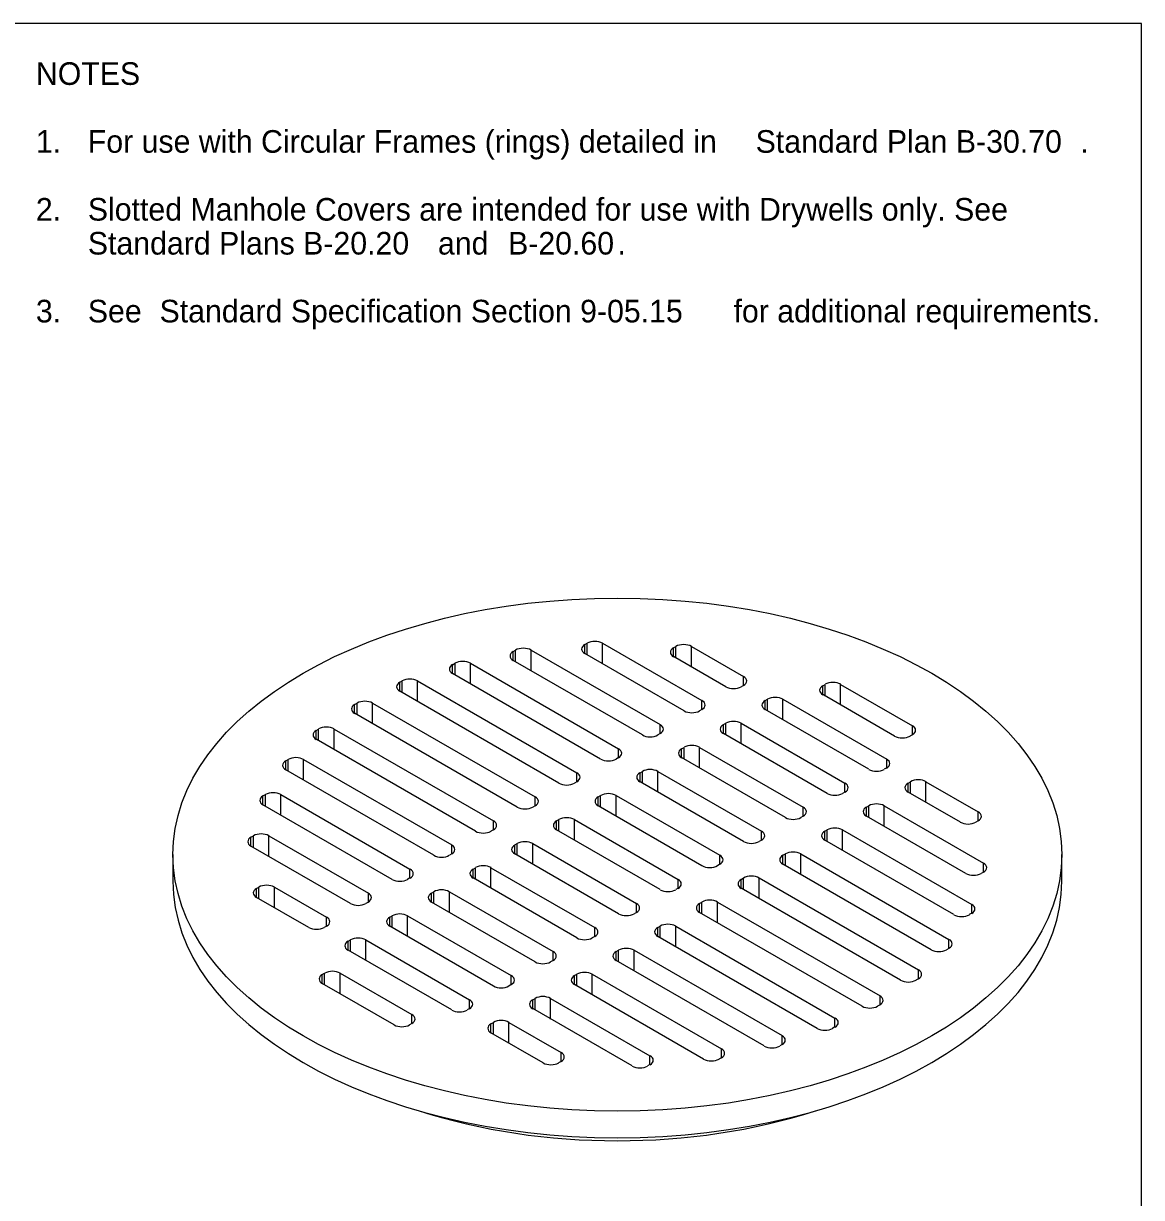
# Model space of a CAD drawing. Extents: x 99862 to 103151, y 100000 to 102076.
# Drawn here: x 102163 to 103151, y 101038 to 102076 of the extents above; entities that cross this region are included whole.
import ezdxf

# ---------------------------------------------------------------- set-up
doc = ezdxf.new("R2010")
doc.units = 0
for name, color, linetype in [('Level 1', 7, 'Continuous'), ('Level 18', 7, 'Continuous'), ('Level 20', 7, 'Continuous'), ('Level 60', 7, 'Continuous')]:
    doc.layers.add(name, color=color, linetype=linetype)

msp = doc.modelspace()

# ---------------------------------------------------------------- linework, layer by layer
at = {"layer": 'Level 1'}
msp.add_lwpolyline([(99862, 99999.5), (103151, 99999.5), (103151, 102075.5), (99862, 102075.5)], close=True, dxfattribs=at)
at = {"layer": 'Level 18'}
for p, q in [((102658.9, 101526.3), (102661, 101527.6)), ((102661, 101517.2), (102661, 101527.6)), ((102674.7, 101527.6), (102762.5, 101476.9)), ((102674.7, 101509.3), (102674.7, 101527.6)), ((102595.8, 101520.2), (102597.9, 101521.5)), ((102595.8, 101512.3), (102595.8, 101520.2)), ((102597.9, 101511.1), (102597.9, 101521.5)), ((102611.6, 101521.5), (102725.7, 101455.6)), ((102611.6, 101503.2), (102611.6, 101521.5)), ((102658.9, 101518.4), (102658.9, 101526.3)), ((102746.7, 101467.7), (102658.9, 101518.4)), ((102737.5, 101523.6), (102739.6, 101524.8)), ((102737.5, 101515.7), (102737.5, 101523.6)), ((102739.6, 101514.4), (102739.6, 101524.8)), ((102753.3, 101524.8), (102799.4, 101498.1)), ((102753.3, 101506.5), (102753.3, 101524.8)), ((102542.2, 101508.6), (102544.3, 101509.9)), ((102542.2, 101500.7), (102542.2, 101508.6)), ((102544.3, 101499.5), (102544.3, 101509.9)), ((102558, 101509.9), (102688.8, 101434.3)), ((102558, 101491.6), (102558, 101509.9)), ((102709.9, 101446.5), (102595.8, 101512.3)), ((102783.6, 101489), (102737.5, 101515.7)), ((102673, 101425.2), (102542.2, 101500.7)), ((102799.4, 101490.2), (102799.4, 101498.1)), ((102495.4, 101493.1), (102497.5, 101494.3)), ((102495.4, 101485.2), (102495.4, 101493.1)), ((102497.5, 101483.9), (102497.5, 101494.3)), ((102511.2, 101494.3), (102652, 101413)), ((102511.2, 101476), (102511.2, 101494.3)), ((102799.4, 101490.2), (102797.3, 101489)), ((102869.3, 101490), (102871.4, 101491.2)), ((102869.3, 101482.1), (102869.3, 101490)), ((102871.4, 101480.9), (102871.4, 101491.2)), ((102885.1, 101491.2), (102948.5, 101454.6)), ((102885.1, 101473), (102885.1, 101491.2)), ((102636.2, 101403.9), (102495.4, 101485.2)), ((102762.5, 101469), (102762.5, 101476.9)), ((102818.4, 101476.9), (102820.5, 101478.1)), ((102818.4, 101469), (102818.4, 101476.9)), ((102820.5, 101467.7), (102820.5, 101478.1)), ((102834.1, 101478.1), (102925.8, 101425.2)), ((102834.1, 101459.8), (102834.1, 101478.1)), ((102932.7, 101445.5), (102869.3, 101482.1)), ((102455.6, 101473.5), (102457.7, 101474.7)), ((102455.6, 101465.6), (102455.6, 101473.5)), ((102599.3, 101382.6), (102455.6, 101465.6)), ((102457.7, 101464.3), (102457.7, 101474.7)), ((102471.4, 101474.7), (102615.1, 101391.7)), ((102471.4, 101456.4), (102471.4, 101474.7)), ((102762.5, 101469), (102760.4, 101467.7)), ((102910, 101416.1), (102818.4, 101469)), ((102725.7, 101447.7), (102725.7, 101455.6)), ((102781.5, 101455.6), (102783.6, 101456.8)), ((102781.5, 101447.7), (102781.5, 101455.6)), ((102783.6, 101446.5), (102783.6, 101456.8)), ((102797.3, 101456.8), (102888.9, 101403.9)), ((102797.3, 101438.6), (102797.3, 101456.8)), ((102948.5, 101446.7), (102948.5, 101454.6)), ((102421.7, 101450.5), (102423.8, 101451.7)), ((102421.7, 101442.6), (102421.7, 101450.5)), ((102423.8, 101441.4), (102423.8, 101451.7)), ((102437.5, 101451.7), (102578.2, 101370.5)), ((102437.5, 101433.5), (102437.5, 101451.7)), ((102725.7, 101447.7), (102723.6, 101446.5)), ((102873.1, 101394.8), (102781.5, 101447.7)), ((102948.5, 101446.7), (102946.4, 101445.5)), ((102562.4, 101361.3), (102421.7, 101442.6)), ((102688.8, 101426.4), (102688.8, 101434.3)), ((102744.6, 101434.3), (102746.7, 101435.5)), ((102744.6, 101426.4), (102744.6, 101434.3)), ((102746.7, 101425.2), (102746.7, 101435.5)), ((102760.4, 101435.5), (102852.1, 101382.6)), ((102760.4, 101417.3), (102760.4, 101435.5)), ((102394.7, 101423.5), (102396.8, 101424.7)), ((102394.7, 101415.6), (102394.7, 101423.5)), ((102396.8, 101414.4), (102396.8, 101424.7)), ((102410.5, 101424.7), (102541.4, 101349.2)), ((102410.5, 101406.5), (102410.5, 101424.7)), ((102688.8, 101426.4), (102686.7, 101425.2)), ((102836.3, 101373.5), (102744.6, 101426.4)), ((102925.8, 101417.3), (102925.8, 101425.2)), ((102525.6, 101340.1), (102394.7, 101415.6)), ((102652, 101405.1), (102652, 101413)), ((102707.8, 101413), (102709.9, 101414.2)), ((102707.8, 101405.1), (102707.8, 101413)), ((102709.9, 101403.9), (102709.9, 101414.2)), ((102723.6, 101414.2), (102815.2, 101361.3)), ((102723.6, 101396), (102723.6, 101414.2)), ((102925.8, 101417.3), (102923.7, 101416.1)), ((102652, 101405.1), (102649.9, 101403.9)), ((102799.4, 101352.2), (102707.8, 101405.1)), ((102888.9, 101396), (102888.9, 101403.9)), ((102944.7, 101403.9), (102946.8, 101405.1)), ((102944.7, 101396), (102944.7, 101403.9)), ((102946.8, 101394.8), (102946.8, 101405.1)), ((102960.5, 101405.1), (103006.6, 101378.5)), ((102960.5, 101386.9), (102960.5, 101405.1)), ((102374.6, 101392.6), (102376.7, 101393.8)), ((102374.6, 101384.7), (102374.6, 101392.6)), ((102376.7, 101383.4), (102376.7, 101393.8)), ((102390.4, 101393.8), (102504.5, 101327.9)), ((102390.4, 101375.5), (102390.4, 101393.8)), ((102670.9, 101391.7), (102673, 101393)), ((102673, 101382.6), (102673, 101393)), ((102686.7, 101393), (102778.3, 101340.1)), ((102686.7, 101374.7), (102686.7, 101393)), ((102888.9, 101396), (102886.8, 101394.8)), ((102990.9, 101369.4), (102944.7, 101396)), ((102488.7, 101318.8), (102374.6, 101384.7)), ((102615.1, 101383.8), (102613, 101382.6)), ((102615.1, 101383.8), (102615.1, 101391.7)), ((102670.9, 101383.8), (102670.9, 101391.7)), ((102762.5, 101330.9), (102670.9, 101383.8)), ((102852.1, 101374.7), (102852.1, 101382.6)), ((102907.9, 101382.6), (102910, 101383.8)), ((102907.9, 101374.7), (102907.9, 101382.6)), ((102910, 101373.5), (102910, 101383.8)), ((102923.7, 101383.8), (103011.5, 101333.1)), ((102923.7, 101365.6), (102923.7, 101383.8)), ((102634.1, 101370.5), (102636.2, 101371.7)), ((102636.2, 101361.3), (102636.2, 101371.7)), ((102649.9, 101371.7), (102741.5, 101318.8)), ((102649.9, 101353.4), (102649.9, 101371.7)), ((102852.1, 101374.7), (102849.9, 101373.5)), ((102995.7, 101324), (102907.9, 101374.7)), ((103006.6, 101370.6), (103006.6, 101378.5)), ((102578.2, 101362.6), (102576.1, 101361.3)), ((102578.2, 101362.6), (102578.2, 101370.5)), ((102634.1, 101362.6), (102634.1, 101370.5)), ((102725.7, 101309.7), (102634.1, 101362.6)), ((102815.2, 101353.4), (102815.2, 101361.3)), ((102871, 101361.3), (102873.1, 101362.6)), ((102871, 101353.4), (102871, 101361.3)), ((102873.1, 101352.2), (102873.1, 101362.6)), ((102886.8, 101362.6), (103000.9, 101296.7)), ((102886.8, 101344.3), (102886.8, 101362.6)), ((103006.6, 101370.6), (103004.5, 101369.4)), ((102364, 101356.1), (102366.2, 101357.3)), ((102364, 101348.2), (102364, 101356.1)), ((102366.2, 101347), (102366.2, 101357.3)), ((102379.8, 101357.3), (102467.7, 101306.6)), ((102379.8, 101339.1), (102379.8, 101357.3)), ((102597.2, 101349.2), (102599.3, 101350.4)), ((102599.3, 101340.1), (102599.3, 101350.4)), ((102613, 101350.4), (102704.6, 101297.5)), ((102613, 101332.2), (102613, 101350.4)), ((102815.2, 101353.4), (102813.1, 101352.2)), ((102985.1, 101287.6), (102871, 101353.4)), ((102295, 101340.7), (102295, 101317.2)), ((102451.9, 101297.5), (102364, 101348.2)), ((102541.4, 101341.3), (102539.3, 101340.1)), ((102541.4, 101341.3), (102541.4, 101349.2)), ((102597.2, 101341.3), (102597.2, 101349.2)), ((102688.8, 101288.4), (102597.2, 101341.3)), ((102778.3, 101332.2), (102778.3, 101340.1)), ((102834.1, 101340.1), (102836.3, 101341.3)), ((102834.1, 101332.2), (102834.1, 101340.1)), ((102836.3, 101330.9), (102836.3, 101341.3)), ((102849.9, 101341.3), (102980.8, 101265.7)), ((102849.9, 101323), (102849.9, 101341.3)), ((103080.6, 101317.2), (103080.6, 101340.7)), ((102778.3, 101332.2), (102776.2, 101330.9)), ((102965, 101256.6), (102834.1, 101332.2)), ((103011.5, 101325.2), (103011.5, 101333.1)), ((102504.5, 101320), (102502.4, 101318.8)), ((102504.5, 101320), (102504.5, 101327.9)), ((102560.3, 101327.9), (102562.4, 101329.1)), ((102560.3, 101320), (102560.3, 101327.9)), ((102652, 101267.1), (102560.3, 101320)), ((102562.4, 101318.8), (102562.4, 101329.1)), ((102576.1, 101329.1), (102667.8, 101276.2)), ((102576.1, 101310.9), (102576.1, 101329.1)), ((102797.3, 101318.8), (102799.4, 101320)), ((102799.4, 101309.7), (102799.4, 101320)), ((102813.1, 101320), (102953.8, 101238.7)), ((102813.1, 101301.8), (102813.1, 101320)), ((103011.5, 101325.2), (103009.4, 101324)), ((102368.9, 101310.7), (102371, 101312)), ((102368.9, 101302.8), (102368.9, 101310.7)), ((102371, 101301.6), (102371, 101312)), ((102384.7, 101312), (102430.8, 101285.3)), ((102384.7, 101293.7), (102384.7, 101312)), ((102741.5, 101310.9), (102739.4, 101309.7)), ((102741.5, 101310.9), (102741.5, 101318.8)), ((102797.3, 101310.9), (102797.3, 101318.8)), ((102938, 101229.6), (102797.3, 101310.9)), ((102415, 101276.2), (102368.9, 101302.8)), ((102467.7, 101298.7), (102465.6, 101297.5)), ((102467.7, 101298.7), (102467.7, 101306.6)), ((102523.5, 101306.6), (102525.6, 101307.8)), ((102523.5, 101298.7), (102523.5, 101306.6)), ((102615.1, 101245.8), (102523.5, 101298.7)), ((102525.6, 101297.5), (102525.6, 101307.8)), ((102539.3, 101307.8), (102630.9, 101254.9)), ((102539.3, 101289.6), (102539.3, 101307.8)), ((102760.4, 101297.5), (102762.5, 101298.7)), ((102762.5, 101288.4), (102762.5, 101298.7)), ((102776.2, 101298.7), (102919.9, 101215.8)), ((102776.2, 101280.5), (102776.2, 101298.7)), ((102704.6, 101289.6), (102702.5, 101288.4)), ((102704.6, 101289.6), (102704.6, 101297.5)), ((102760.4, 101289.6), (102760.4, 101297.5)), ((102904.1, 101206.6), (102760.4, 101289.6)), ((103000.9, 101288.8), (102998.8, 101287.6)), ((103000.9, 101288.8), (103000.9, 101296.7)), ((102430.8, 101277.4), (102430.8, 101285.3)), ((102486.6, 101285.3), (102488.7, 101286.5)), ((102486.6, 101277.4), (102486.6, 101285.3)), ((102488.7, 101276.2), (102488.7, 101286.5)), ((102502.4, 101286.5), (102594, 101233.7)), ((102502.4, 101268.3), (102502.4, 101286.5)), ((102430.8, 101277.4), (102428.7, 101276.2)), ((102578.2, 101224.5), (102486.6, 101277.4)), ((102667.8, 101268.3), (102665.6, 101267.1)), ((102667.8, 101268.3), (102667.8, 101276.2)), ((102723.6, 101276.2), (102725.7, 101277.4)), ((102723.6, 101268.3), (102723.6, 101276.2)), ((102864.3, 101187), (102723.6, 101268.3)), ((102725.7, 101267.1), (102725.7, 101277.4)), ((102739.4, 101277.4), (102880.1, 101196.2)), ((102739.4, 101259.2), (102739.4, 101277.4)), ((102449.8, 101264.1), (102451.9, 101265.3)), ((102449.8, 101256.1), (102449.8, 101264.1)), ((102451.9, 101254.9), (102451.9, 101265.3)), ((102465.6, 101265.3), (102557.2, 101212.4)), ((102465.6, 101247), (102465.6, 101265.3)), ((102980.8, 101257.8), (102978.7, 101256.6)), ((102980.8, 101257.8), (102980.8, 101265.7)), ((102541.4, 101203.3), (102449.8, 101256.1)), ((102630.9, 101247), (102628.8, 101245.8)), ((102630.9, 101247), (102630.9, 101254.9)), ((102686.7, 101254.9), (102688.8, 101256.1)), ((102686.7, 101247), (102686.7, 101254.9)), ((102817.6, 101171.5), (102686.7, 101247)), ((102688.8, 101245.8), (102688.8, 101256.1)), ((102702.5, 101256.1), (102833.4, 101180.6)), ((102702.5, 101237.9), (102702.5, 101256.1)), ((102953.8, 101230.8), (102953.8, 101238.7)), ((102427, 101234.6), (102429.1, 101235.8)), ((102427, 101226.7), (102427, 101234.6)), ((102490.4, 101190.1), (102427, 101226.7)), ((102429.1, 101225.5), (102429.1, 101235.8)), ((102442.8, 101235.8), (102506.2, 101199.2)), ((102442.8, 101217.6), (102442.8, 101235.8)), ((102594, 101225.7), (102594, 101233.7)), ((102649.9, 101233.7), (102652, 101234.9)), ((102649.9, 101225.7), (102649.9, 101233.7)), ((102652, 101224.5), (102652, 101234.9)), ((102665.6, 101234.9), (102779.8, 101169)), ((102665.6, 101216.6), (102665.6, 101234.9)), ((102953.8, 101230.8), (102951.7, 101229.6)), ((102594, 101225.7), (102591.9, 101224.5)), ((102764, 101159.9), (102649.9, 101225.7)), ((102919.9, 101207.9), (102919.9, 101215.8)), ((102557.2, 101204.5), (102557.2, 101212.4)), ((102613, 101212.4), (102615.1, 101213.6)), ((102613, 101204.5), (102613, 101212.4)), ((102615.1, 101203.3), (102615.1, 101213.6)), ((102628.8, 101213.6), (102716.6, 101162.9)), ((102628.8, 101195.3), (102628.8, 101213.6)), ((102919.9, 101207.9), (102917.8, 101206.6)), ((102506.2, 101191.3), (102506.2, 101199.2)), ((102557.2, 101204.5), (102555.1, 101203.3)), ((102700.8, 101153.8), (102613, 101204.5)), ((102880.1, 101188.3), (102880.1, 101196.2)), ((102506.2, 101191.3), (102504.1, 101190.1)), ((102576.1, 101191.1), (102578.2, 101192.3)), ((102576.1, 101183.2), (102576.1, 101191.1)), ((102578.2, 101182), (102578.2, 101192.3)), ((102591.9, 101192.3), (102638.1, 101165.7)), ((102591.9, 101174.1), (102591.9, 101192.3)), ((102880.1, 101188.3), (102878, 101187)), ((102622.3, 101156.6), (102576.1, 101183.2)), ((102833.4, 101172.7), (102833.4, 101180.6)), ((102638.1, 101157.8), (102638.1, 101165.7)), ((102779.8, 101161.1), (102779.8, 101169)), ((102833.4, 101172.7), (102831.3, 101171.5)), ((102638.1, 101157.8), (102635.9, 101156.6)), ((102716.6, 101155), (102714.5, 101153.8)), ((102716.6, 101155), (102716.6, 101162.9)), ((102779.8, 101161.1), (102777.6, 101159.9))]:
    msp.add_line(p, q, dxfattribs=at)
msp.add_ellipse((102687.8, 101340.7), major_axis=(392.8, 0), ratio=0.57735, dxfattribs=at)
for centre, major_axis, start_param, end_param in [((102667.9, 101523.6), (-9.68, 0), 3.926991, 5.497787), ((102746.4, 101520.8), (-9.68, 0), 3.926991, 5.497787), ((102602.6, 101516.3), (-9.68, 0), 5.497787, 7.068583), ((102604.7, 101517.5), (-9.68, 0), 3.926991, 5.497787), ((102665.8, 101522.4), (-9.68, 0), 5.497787, 7.068583), ((102744.3, 101519.6), (-9.68, 0), 5.497787, 7.068583), ((102549, 101504.7), (-9.68, 0), 5.497787, 7.068583), ((102551.1, 101505.9), (-9.68, 0), 3.926991, 5.497787), ((102504.4, 101490.3), (-9.68, 0), 3.926991, 5.497787), ((102792.5, 101494.2), (-9.68, 0), 2.356194, 3.926991), ((102502.3, 101489.1), (-9.68, 0), 5.497787, 7.068583), ((102790.4, 101493), (-9.68, 0), 0.785398, 2.356194), ((102876.2, 101486), (-9.68, 0), 5.497787, 7.068583), ((102878.3, 101487.3), (-9.68, 0), 3.926991, 5.497787), ((102464.6, 101470.7), (-9.68, 0), 3.926991, 5.497787), ((102755.7, 101472.9), (-9.68, 0), 2.356194, 3.926991), ((102825.2, 101472.9), (-9.68, 0), 5.497787, 7.068583), ((102827.3, 101474.1), (-9.68, 0), 3.926991, 5.497787), ((102462.5, 101469.5), (-9.68, 0), 5.497787, 7.068583), ((102753.6, 101471.7), (-9.68, 0), 0.785398, 2.356194), ((102718.8, 101451.6), (-9.68, 0), 2.356194, 3.926991), ((102788.3, 101451.6), (-9.68, 0), 5.497787, 7.068583), ((102790.4, 101452.8), (-9.68, 0), 3.926991, 5.497787), ((102941.7, 101450.7), (-9.68, 0), 2.356194, 3.926991), ((102428.5, 101446.5), (-9.68, 0), 5.497787, 7.068583), ((102430.6, 101447.8), (-9.68, 0), 3.926991, 5.497787), ((102716.7, 101450.4), (-9.68, 0), 0.785398, 2.356194), ((102939.6, 101449.4), (-9.68, 0), 0.785398, 2.356194), ((102682, 101430.3), (-9.68, 0), 2.356194, 3.926991), ((102751.5, 101430.3), (-9.68, 0), 5.497787, 7.068583), ((102753.6, 101431.6), (-9.68, 0), 3.926991, 5.497787), ((102401.6, 101419.6), (-9.68, 0), 5.497787, 7.068583), ((102403.7, 101420.8), (-9.68, 0), 3.926991, 5.497787), ((102679.9, 101429.1), (-9.68, 0), 0.785398, 2.356194), ((102918.9, 101421.2), (-9.68, 0), 2.356194, 3.926991), ((102645.1, 101409.1), (-9.68, 0), 2.356194, 3.926991), ((102714.6, 101409.1), (-9.68, 0), 5.497787, 7.068583), ((102716.7, 101410.3), (-9.68, 0), 3.926991, 5.497787), ((102916.8, 101420), (-9.68, 0), 0.785398, 2.356194), ((102643, 101407.8), (-9.68, 0), 0.785398, 2.356194), ((102882.1, 101399.9), (-9.68, 0), 2.356194, 3.926991), ((102951.6, 101399.9), (-9.68, 0), 5.497787, 7.068583), ((102953.7, 101401.2), (-9.68, 0), 3.926991, 5.497787), ((102381.5, 101388.6), (-9.68, 0), 5.497787, 7.068583), ((102383.6, 101389.8), (-9.68, 0), 3.926991, 5.497787), ((102679.9, 101389), (-9.68, 0), 3.926991, 5.497787), ((102880, 101398.7), (-9.68, 0), 0.785398, 2.356194), ((102606.1, 101386.6), (-9.68, 0), 0.785398, 2.356194), ((102608.3, 101387.8), (-9.68, 0), 2.356194, 3.926991), ((102677.8, 101387.8), (-9.68, 0), 5.497787, 7.068583), ((102845.2, 101378.7), (-9.68, 0), 2.356194, 3.926991), ((102914.7, 101378.7), (-9.68, 0), 5.497787, 7.068583), ((102916.8, 101379.9), (-9.68, 0), 3.926991, 5.497787), ((102643, 101367.7), (-9.68, 0), 3.926991, 5.497787), ((102843.1, 101377.4), (-9.68, 0), 0.785398, 2.356194), ((102999.8, 101374.5), (-9.68, 0), 2.356194, 3.926991), ((102569.3, 101365.3), (-9.68, 0), 0.785398, 2.356194), ((102571.4, 101366.5), (-9.68, 0), 2.356194, 3.926991), ((102640.9, 101366.5), (-9.68, 0), 5.497787, 7.068583), ((102808.3, 101357.4), (-9.68, 0), 2.356194, 3.926991), ((102877.9, 101357.4), (-9.68, 0), 5.497787, 7.068583), ((102880, 101358.6), (-9.68, 0), 3.926991, 5.497787), ((102997.7, 101373.3), (-9.68, 0), 0.785398, 2.356194), ((102370.9, 101352.1), (-9.68, 0), 5.497787, 7.068583), ((102373, 101353.4), (-9.68, 0), 3.926991, 5.497787), ((102606.1, 101346.4), (-9.68, 0), 3.926991, 5.497787), ((102806.2, 101356.2), (-9.68, 0), 0.785398, 2.356194), ((102532.4, 101344), (-9.68, 0), 0.785398, 2.356194), ((102534.5, 101345.2), (-9.68, 0), 2.356194, 3.926991), ((102604, 101345.2), (-9.68, 0), 5.497787, 7.068583), ((102771.5, 101336.1), (-9.68, 0), 2.356194, 3.926991), ((102841, 101336.1), (-9.68, 0), 5.497787, 7.068583), ((102843.1, 101337.3), (-9.68, 0), 3.926991, 5.497787), ((102569.3, 101325.2), (-9.68, 0), 3.926991, 5.497787), ((102769.4, 101334.9), (-9.68, 0), 0.785398, 2.356194), ((103004.6, 101329.2), (-9.68, 0), 2.356194, 3.926991), ((102497.7, 101323.9), (-9.68, 0), 2.356194, 3.926991), ((102567.2, 101323.9), (-9.68, 0), 5.497787, 7.068583), ((102806.2, 101316), (-9.68, 0), 3.926991, 5.497787), ((103002.5, 101328), (-9.68, 0), 0.785398, 2.356194), ((102687.8, 101317.2), (392.8, 0), 3.141593, 6.283185), ((102375.7, 101306.8), (-9.68, 0), 5.497787, 7.068583), ((102377.8, 101308), (-9.68, 0), 3.926991, 5.497787), ((102495.6, 101322.7), (-9.68, 0), 0.785398, 2.356194), ((102532.4, 101303.9), (-9.68, 0), 3.926991, 5.497787), ((102732.5, 101313.6), (-9.68, 0), 0.785398, 2.356194), ((102734.6, 101314.8), (-9.68, 0), 2.356194, 3.926991), ((102804.1, 101314.8), (-9.68, 0), 5.497787, 7.068583), ((102460.8, 101302.7), (-9.68, 0), 2.356194, 3.926991), ((102530.3, 101302.7), (-9.68, 0), 5.497787, 7.068583), ((102769.4, 101294.8), (-9.68, 0), 3.926991, 5.497787), ((102458.7, 101301.4), (-9.68, 0), 0.785398, 2.356194), ((102495.6, 101282.6), (-9.68, 0), 3.926991, 5.497787), ((102695.7, 101292.3), (-9.68, 0), 0.785398, 2.356194), ((102697.8, 101293.5), (-9.68, 0), 2.356194, 3.926991), ((102767.3, 101293.5), (-9.68, 0), 5.497787, 7.068583), ((102994.1, 101292.7), (-9.68, 0), 2.356194, 3.926991), ((102424, 101281.4), (-9.68, 0), 2.356194, 3.926991), ((102493.5, 101281.4), (-9.68, 0), 5.497787, 7.068583), ((102732.5, 101273.5), (-9.68, 0), 3.926991, 5.497787), ((102992, 101291.5), (-9.68, 0), 0.785398, 2.356194), ((102421.9, 101280.2), (-9.68, 0), 0.785398, 2.356194), ((102660.9, 101272.3), (-9.68, 0), 2.356194, 3.926991), ((102730.4, 101272.3), (-9.68, 0), 5.497787, 7.068583), ((102456.6, 101260.1), (-9.68, 0), 5.497787, 7.068583), ((102458.7, 101261.3), (-9.68, 0), 3.926991, 5.497787), ((102658.8, 101271), (-9.68, 0), 0.785398, 2.356194), ((102695.7, 101252.2), (-9.68, 0), 3.926991, 5.497787), ((102974, 101261.8), (-9.68, 0), 2.356194, 3.926991), ((102624.1, 101251), (-9.68, 0), 2.356194, 3.926991), ((102693.6, 101251), (-9.68, 0), 5.497787, 7.068583), ((102971.9, 101260.5), (-9.68, 0), 0.785398, 2.356194), ((102436, 101231.9), (-9.68, 0), 3.926991, 5.497787), ((102621.9, 101249.8), (-9.68, 0), 0.785398, 2.356194), ((102658.8, 101230.9), (-9.68, 0), 3.926991, 5.497787), ((102947, 101234.8), (-9.68, 0), 2.356194, 3.926991), ((102433.9, 101230.7), (-9.68, 0), 5.497787, 7.068583), ((102587.2, 101229.7), (-9.68, 0), 2.356194, 3.926991), ((102656.7, 101229.7), (-9.68, 0), 5.497787, 7.068583), ((102944.9, 101233.6), (-9.68, 0), 0.785398, 2.356194), ((102585.1, 101228.5), (-9.68, 0), 0.785398, 2.356194), ((102621.9, 101209.6), (-9.68, 0), 3.926991, 5.497787), ((102913, 101211.8), (-9.68, 0), 2.356194, 3.926991), ((102550.3, 101208.4), (-9.68, 0), 2.356194, 3.926991), ((102619.8, 101208.4), (-9.68, 0), 5.497787, 7.068583), ((102910.9, 101210.6), (-9.68, 0), 0.785398, 2.356194), ((102499.4, 101195.3), (-9.68, 0), 2.356194, 3.926991), ((102548.2, 101207.2), (-9.68, 0), 0.785398, 2.356194), ((102873.3, 101192.2), (-9.68, 0), 2.356194, 3.926991), ((102497.3, 101194.1), (-9.68, 0), 0.785398, 2.356194), ((102583, 101187.1), (-9.68, 0), 5.497787, 7.068583), ((102585.1, 101188.4), (-9.68, 0), 3.926991, 5.497787), ((102871.2, 101191), (-9.68, 0), 0.785398, 2.356194), ((102826.5, 101176.6), (-9.68, 0), 2.356194, 3.926991), ((102631.2, 101161.7), (-9.68, 0), 2.356194, 3.926991), ((102772.9, 101165), (-9.68, 0), 2.356194, 3.926991), ((102824.4, 101175.4), (-9.68, 0), 0.785398, 2.356194), ((102629.1, 101160.5), (-9.68, 0), 0.785398, 2.356194), ((102707.7, 101157.7), (-9.68, 0), 0.785398, 2.356194), ((102709.8, 101158.9), (-9.68, 0), 2.356194, 3.926991), ((102770.8, 101163.8), (-9.68, 0), 0.785398, 2.356194), ((102687.8, 101293.7), (356.8, 0), 4.199654, 5.225124)]:
    msp.add_ellipse(centre, major_axis=major_axis, ratio=0.57735, start_param=start_param, end_param=end_param, dxfattribs=at)
at = {"layer": 'Level 60'}
msp.add_line((103151, 102075.5), (103151, 102075.5), dxfattribs=at)

# ---------------------------------------------------------------- texts
at = {"layer": 'Level 20'}
for s, p in [('NOTES', (102173.9, 102021.2)), ('1.', (102173.9, 101961.2)), ('For use with Circular Frames (rings) detailed in ', (102219.8, 101961.2)), ('Standard Plan B-30.70', (102810, 101961.2)), ('.', (103096.9, 101961.2)), ('2.', (102173.9, 101901.2)), ('Slotted Manhole Covers are intended for use with Drywells only. See', (102219.8, 101901.2)), ('Standard Plans B-20.20', (102219.8, 101871.2)), (' and ', (102521.8, 101871.2)), ('B-20.60', (102591.2, 101871.2)), ('.', (102687.9, 101871.2)), ('3.', (102173.9, 101811.2)), ('See ', (102219.8, 101811.2)), ('Standard Specification Section 9-05.15', (102283.2, 101811.2)), (' for additional requirements.', (102783, 101811.2))]:
    msp.add_text(s, height=20, dxfattribs=at).set_placement(p)

doc.saveas('drawing.dxf')
